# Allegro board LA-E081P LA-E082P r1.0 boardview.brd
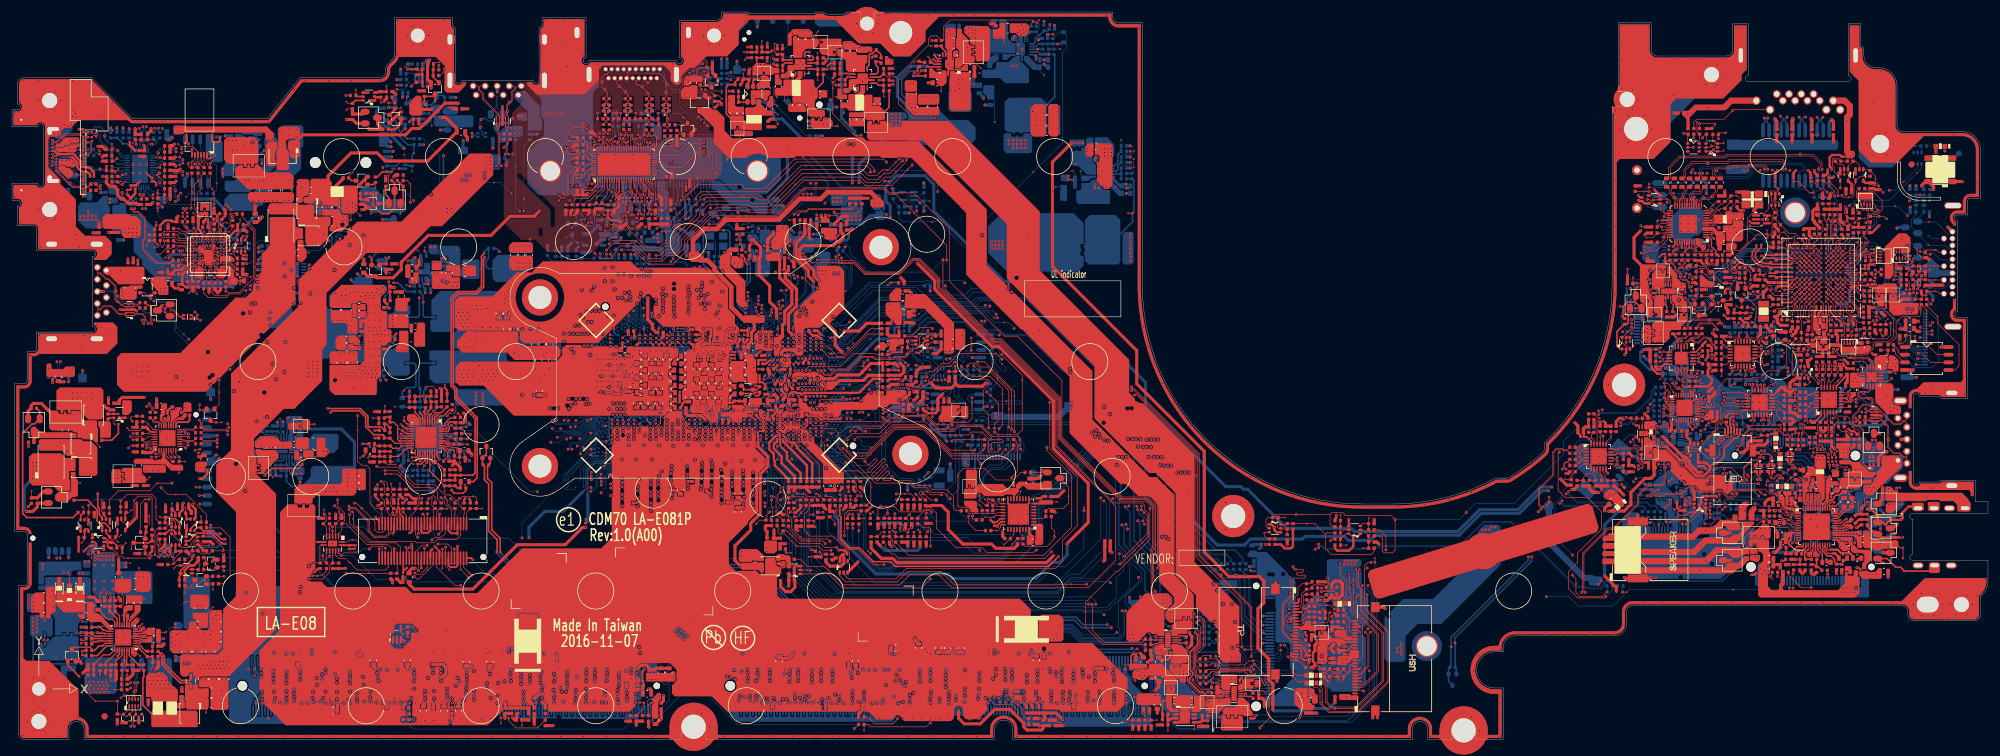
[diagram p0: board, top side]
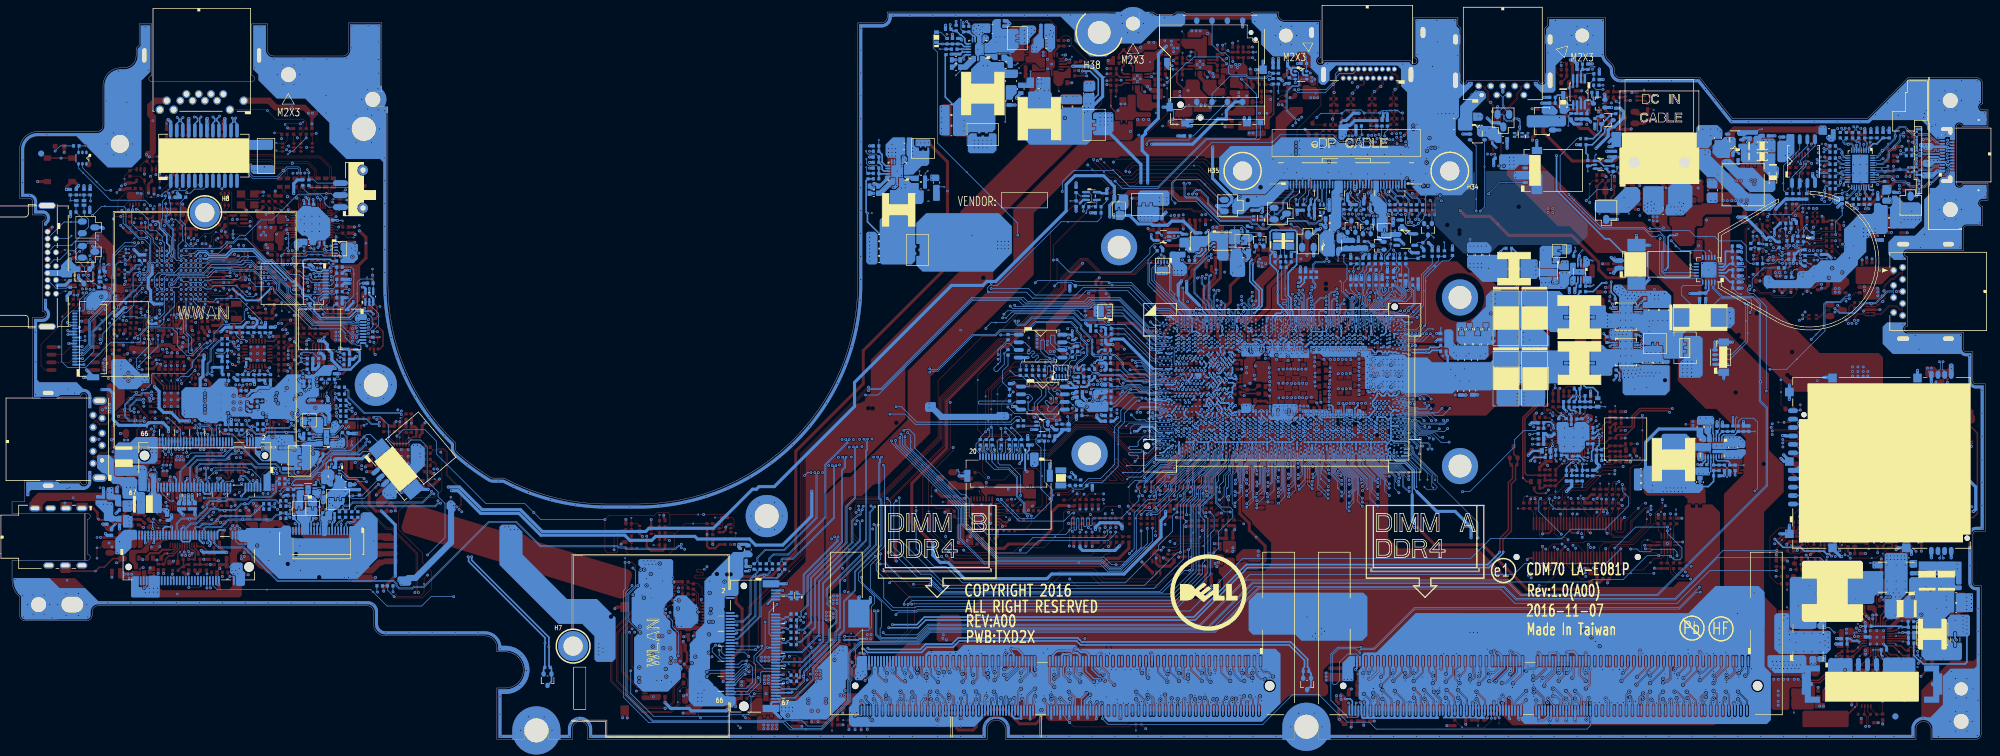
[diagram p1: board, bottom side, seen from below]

Outline 328.05 x 120.8 mm; copper layers: TOP, GND1, IN1, GND2, IN2, IN3, VCC, IN4, GND3, BOTTOM. Coordinates in mm from the lower left corner of the outline.

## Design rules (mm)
net group CLK_ITPXDP_: nets CLK_ITPXDP_N CLK_ITPXDP_P
net group CPU_DP2_0_C: nets CPU_DP2_N0_C CPU_DP2_P0_C
net group CPU_DP2_1_C: nets CPU_DP2_N1_C CPU_DP2_P1_C
net group CPU_DP2_2_C: nets CPU_DP2_N2_C CPU_DP2_P2_C
net group CPU_DP2_3_C: nets CPU_DP2_N3_C CPU_DP2_P3_C
net group CPU_DP2_AUX_C: nets CPU_DP2_AUXN_C CPU_DP2_AUXP_C
net group CPU_DP3_AUX: nets CPU_DP3_AUXN CPU_DP3_AUXP
net group CRT_CTL_5_10: nets CLK_DDC2_CRT DAT_DDC2_CRT
net group CSI_ISL88738: nets CSIN_ISL88738 CSIP_ISL88738
net group CSO_ISL88738: nets CSON_ISL88738 CSOP_ISL88738
net group DDR_A_0: nets DDR_A_DQS0 DDR_A_DQS#0
net group DDR_A_1: nets DDR_A_DQS1 DDR_A_DQS#1
net group DDR_A_2: nets DDR_A_DQS2 DDR_A_DQS#2
net group DDR_A_3: nets DDR_A_DQS3 DDR_A_DQS#3
net group DDR_A_4: nets DDR_A_DQS4 DDR_A_DQS#4
net group DDR_A_5: nets DDR_A_DQS5 DDR_A_DQS#5
net group DDR_A_6: nets DDR_A_DQS6 DDR_A_DQS#6
net group DDR_A_7: nets DDR_A_DQS7 DDR_A_DQS#7
net group DDR_A_CLK0: nets DDR_A_CLK0 DDR_A_CLK#0
net group DDR_A_CLK1: nets DDR_A_CLK1 DDR_A_CLK#1
net group DDR_B_0: nets DDR_B_DQS0 DDR_B_DQS#0
net group DDR_B_1: nets DDR_B_DQS1 DDR_B_DQS#1
net group DDR_B_2: nets DDR_B_DQS2 DDR_B_DQS#2
net group DDR_B_3: nets DDR_B_DQS3 DDR_B_DQS#3
net group DDR_B_4: nets DDR_B_DQS4 DDR_B_DQS#4
net group DDR_B_5: nets DDR_B_DQS5 DDR_B_DQS#5
net group DDR_B_6: nets DDR_B_DQS6 DDR_B_DQS#6
net group DDR_B_7: nets DDR_B_DQS7 DDR_B_DQS#7
net group DDR_B_CLK0: nets DDR_B_CLK0 DDR_B_CLK#0
net group DDR_B_CLK1: nets DDR_B_CLK1 DDR_B_CLK#1
net group DIFFPAIR0: nets SML0_SMBCLK SML0_SMBDATA
net group DIFFPAIR2: nets CLK_TP_SIO_I2C_DAT DAT_TP_SIO_I2C_CLK
net group DIFFPAIR3: nets I2C1_SCK_TP I2C1_SDA_TP
net group DIFFPAIR4: nets I2C1_SCK_TP_R I2C1_SDA_TP_R
net group DIFFPAIR5: nets CLK_TP_SIO_R DAT_TP_SIO_R
net group DIFFPAIR9: nets EXPANDER_GPU_SMCLK EXPANDER_GPU_SMDAT
net group DIFFPAIR12: nets ISH_I2C2_SCL_R ISH_I2C2_SDA_R
net group DIFFPAIR13: nets ISH_I2C2_SCL ISH_I2C2_SDA
net group DIFFPAIR14: nets ISPSCL ISPSDA
net group DIFFPAIR18: nets PCH_CL_CLK1 PCH_CL_DATA1
net group DIFFPAIR19: nets UIM_CLK UIM_DATA
net group DIFFPAIR21: nets MUX1_DP_SEL MUX1_USB_SEL
net group DIFFPAIR22: nets UPD1_SMBCLK_Q UPD1_SMBDAT_Q
net group DIFFPAIR31: nets UPD1_SMBCLK UPD1_SMBDAT
net group DIFFPAIR36: nets VCCIO_SENSE VSSIO_SENSE
net group DIFFPAIR37: nets UPD2_SMBCLK UPD2_SMBDAT
net group DIFFPAIR45: nets TUSB546A_SBU1_R TUSB546A_SBU2_R
net group DIFFPAIR46: nets TBTA_SBU1_R TBTA_SBU2_R
net group DIFFPAIR47: nets TBTA_SBU1 TBTA_SBU2
net group DIFFPAIR48: nets TBTA_CC1 TBTA_CC2
net group DIFFPAIR49: nets VCCSENSE VSSSENSE
net group DIFFPAIR50: nets VCC_GT_SENSE VSS_GT_SENSE
net group DP: nets CPU_DP1_AUXN CPU_DP1_AUXP
net group EDP_AUX_C: nets EDP_AUXN_C EDP_AUXP_C
net group EDP_TX0_C: nets EDP_TXN0_C EDP_TXP0_C
net group EDP_TX1_C: nets EDP_TXN1_C EDP_TXP1_C
net group HDMI: nets CPU_DP2_CTRL_CLK CPU_DP2_CTRL_DATA
net group HDMI-CTL: nets HDMI_CTRL_CLK HDMI_CTRL_DATA
net group HDMI_CLK: nets HDMI_CLKN HDMI_CLKP
net group HDMI_L_CLK: nets HDMI_L_CLKN HDMI_L_CLKP
net group HDMI_L_TX_0: nets HDMI_L_TX_N0 HDMI_L_TX_P0
net group HDMI_L_TX_1: nets HDMI_L_TX_N1 HDMI_L_TX_P1
net group HDMI_L_TX_2: nets HDMI_L_TX_N2 HDMI_L_TX_P2
net group HDMI_TX_0: nets HDMI_TX_N0 HDMI_TX_P0
net group HDMI_TX_1: nets HDMI_TX_N1 HDMI_TX_P1
net group HDMI_TX_2: nets HDMI_TX_N2 HDMI_TX_P2
net group LAN_MDI0: nets LAN_MDIN0 LAN_MDIP0
net group LAN_MDI0_L: nets LAN_MDIN0_L LAN_MDIP0_L
net group LAN_MDI1: nets LAN_MDIN1 LAN_MDIP1
net group LAN_MDI1_L: nets LAN_MDIN1_L LAN_MDIP1_L
net group LAN_MDI2: nets LAN_MDIN2 LAN_MDIP2
net group LAN_MDI2_L: nets LAN_MDIN2_L LAN_MDIP2_L
net group LAN_MDI3: nets LAN_MDIN3 LAN_MDIP3
net group LAN_MDI3_L: nets LAN_MDIN3_L LAN_MDIP3_L
net group PCIE_RCOMP: nets PCIE_RCOMPN PCIE_RCOMPP
net group REM_DIODE1_: nets REM_DIODE1_N REM_DIODE1_P
net group REM_DIODE2_: nets REM_DIODE2_N REM_DIODE2_P
net group REM_DIODE4_: nets REM_DIODE4_N REM_DIODE4_P
net group RJ45_MDI0: nets RJ45_MDIN0 RJ45_MDIP0
net group RJ45_MDI1: nets RJ45_MDIN1 RJ45_MDIP1
net group RJ45_MDI2: nets RJ45_MDIN2 RJ45_MDIP2
net group RJ45_MDI3: nets RJ45_MDIN3 RJ45_MDIP3
net group SD/MMCDAT1/RCLK-: nets SD/MMCDAT0/RCLK+ SD/MMCDAT1/RCLK-
net group SD/MMCDAT1/RCLK-_R: nets SD/MMCDAT0/RCLK+_R SD/MMCDAT1/RCLK-_R
net group SD_UHS2_D0: nets SD_UHS2_D0N SD_UHS2_D0P
net group SD_UHS2_D1: nets SD_UHS2_D1N SD_UHS2_D1P
net group SW2_DP1_0_C: nets SW2_DP1_N0_C SW2_DP1_P0_C
net group SW2_DP1_1_C: nets SW2_DP1_N1_C SW2_DP1_P1_C
net group SW2_DP1_2_C: nets SW2_DP1_N2_C SW2_DP1_P2_C
net group SW2_DP1_3_C: nets SW2_DP1_N3_C SW2_DP1_P3_C
net group SW2_DP1_AUX_C: nets SW2_DP1_AUXN_C SW2_DP1_AUXP_C
net group SW2_DP2_0_C: nets SW2_DP2_N0_C SW2_DP2_P0_C
net group SW2_DP2_1_C: nets SW2_DP2_N1_C SW2_DP2_P1_C
net group SW2_DP2_2_C: nets SW2_DP2_N2_C SW2_DP2_P2_C
net group SW2_DP2_3_C: nets SW2_DP2_N3_C SW2_DP2_P3_C
net group SW2_DP2_AUX_C: nets SW2_DP2_AUXN_C SW2_DP2_AUXP_C
net group SW2_DP3_0_C: nets SW2_DP3_N0_C SW2_DP3_P0_C
net group SW2_DP3_1_C: nets SW2_DP3_N1_C SW2_DP3_P1_C
net group SW2_DP3_AUX_C: nets SW2_DP3_AUXN_C SW2_DP3_AUXP_C
net group SW_USB20_1: nets SW_USB20_N1 SW_USB20_P1
net group THERMAL: nets POWER_SW#_MB POWER_SW_IN#
net group USB3_PRX_C_DTX_6: nets USB3_PRX_C_DTX_N6 USB3_PRX_C_DTX_P6
net group USB3_PRX_C_RD_DTX_1: nets USB3_PRX_C_RD_DTX_N1 USB3_PRX_C_RD_DTX_P1
net group USB3_PRX_L_DTX_2: nets USB3_PRX_L_DTX_N2 USB3_PRX_L_DTX_P2
net group USB3_PRX_RD_DTX_1: nets USB3_PRX_RD_DTX_N1 USB3_PRX_RD_DTX_P1
net group USB3_PTX_C_DRX_1: nets USB3_PTX_C_DRX_N1 USB3_PTX_C_DRX_P1
net group USB3_PTX_C_DRX_2: nets USB3_PTX_C_DRX_N2 USB3_PTX_C_DRX_P2
net group USB3_PTX_C_DRX_3: nets USB3_PTX_C_DRX_N3 USB3_PTX_C_DRX_P3
net group USB3_PTX_C_DRX_4: nets USB3_PTX_C_DRX_N4 USB3_PTX_C_DRX_P4
net group USB3_PTX_C_DRX_6: nets USB3_PTX_C_DRX_N6 USB3_PTX_C_DRX_P6
net group USB3_PTX_C_RD_DRX_1: nets USB3_PTX_C_RD_DRX_N1 USB3_PTX_C_RD_DRX_P1
net group USB3_PTX_L_DRX_2: nets USB3_PTX_L_DRX_N2 USB3_PTX_L_DRX_P2
net group USB3_PTX_RD_DRX_1: nets USB3_PTX_RD_DRX_N1 USB3_PTX_RD_DRX_P1
net group USB20_1_R: nets USB20_N1_R USB20_P1_R
net group USB20_2_R: nets USB20_N2_R USB20_P2_R
net group USB20_3_R: nets USB20_N3_R USB20_P3_R
net group USB20_4_L: nets USB20_N4_L USB20_P4_L
net group USB20_5_R: nets USB20_N5_R USB20_P5_R
net group USB20_7_L: nets USB20_N7_L USB20_P7_L
net group USB20_8_R: nets USB20_N8_R USB20_P8_R
net group 12: nets H_VCCST_PWRGD_XDP
net group 15: nets ESPI_CLK_5105
net group 20: nets +DDR_VREF_A_DQ +DDR_VREF_B_CA +DDR_VREF_B_DQ +DDR_VREF_CA DDR_DRAMRST# DDR_DRAMRST#_R INT_SPK_L+ INT_SPK_L- INT_SPK_R+ INT_SPK_R- INT_SPKR_L+ INT_SPKR_L- INT_SPKR_R+ INT_SPKR_R-
net group 5225: nets CAM_MIC_CBL_DET# CLK_ITPXDP_N_R CLK_ITPXDP_P_R CLK_PCIE_N0 CLK_PCIE_N1 CLK_PCIE_N2 CLK_PCIE_N3 CLK_PCIE_N4 CLK_PCIE_N5 CLK_PCIE_P0 CLK_PCIE_P1 CLK_PCIE_P2 CLK_PCIE_P3 CLK_PCIE_P4 CLK_PCIE_P5 CPU_DP1_CTRL_CLK CPU_DP1_CTRL_DATA CPU_DP1_N0 CPU_DP1_N1 CPU_DP1_N2 CPU_DP1_N3 CPU_DP1_P0 CPU_DP1_P1 CPU_DP1_P2 CPU_DP1_P3 CPU_DP2_AUXN CPU_DP2_AUXP CPU_DP2_N0 CPU_DP2_N1 CPU_DP2_N2 CPU_DP2_N3 CPU_DP2_P0 CPU_DP2_P1 CPU_DP2_P2 CPU_DP2_P3 EDP_AUXN EDP_AUXP EDP_BIA_PWM EDP_HPD EDP_TXN0 EDP_TXN1 EDP_TXP0 EDP_TXP1 ENVDD_PCH LPSS_UART2_RXD LPSS_UART2_TXD PANEL_BKLEN PCIE_PRX_DTX_N1 PCIE_PRX_DTX_N3 PCIE_PRX_DTX_N4 PCIE_PRX_DTX_N11 PCIE_PRX_DTX_N12 PCIE_PRX_DTX_P1 PCIE_PRX_DTX_P3 PCIE_PRX_DTX_P4 PCIE_PRX_DTX_P11 PCIE_PRX_DTX_P12 PCIE_PRX_RD_DTX_N11 PCIE_PRX_RD_DTX_N12 PCIE_PRX_RD_DTX_P11 PCIE_PRX_RD_DTX_P12 PCIE_PTX_DRX_N1 PCIE_PTX_DRX_N3 PCIE_PTX_DRX_N4 PCIE_PTX_DRX_N8 PCIE_PTX_DRX_N9 PCIE_PTX_DRX_N11 PCIE_PTX_DRX_N12 PCIE_PTX_DRX_P1 PCIE_PTX_DRX_P3 PCIE_PTX_DRX_P4 PCIE_PTX_DRX_P8 PCIE_PTX_DRX_P9 PCIE_PTX_DRX_P11 PCIE_PTX_DRX_P12 PCIE_PTX_RD_DRX_N11 PCIE_PTX_RD_DRX_P11 SATA_PRX_DTX_N0 SATA_PRX_DTX_P0 SW2_DP1_AUXN SW2_DP1_AUXP SW2_DP1_N0 SW2_DP1_N1 SW2_DP1_N2 SW2_DP1_N3 SW2_DP1_P0 SW2_DP1_P1 SW2_DP1_P2 SW2_DP1_P3 SW2_DP2_AUXN SW2_DP2_AUXP SW2_DP2_N0 SW2_DP2_N1 SW2_DP2_N2 SW2_DP2_N3 SW2_DP2_P0 SW2_DP2_P1 SW2_DP2_P2 SW2_DP2_P3 SW2_DP3_AUXN SW2_DP3_AUXP SW2_DP3_N0 SW2_DP3_N1 SW2_DP3_P0 SW2_DP3_P1 USB3_PRX_DTX_N1 USB3_PRX_DTX_N2 USB3_PRX_DTX_N3 USB3_PRX_DTX_N4 USB3_PRX_DTX_N6 USB3_PRX_DTX_P1 USB3_PRX_DTX_P2 USB3_PRX_DTX_P3 USB3_PRX_DTX_P4 USB3_PRX_DTX_P6 USB3_PTX_DRX_N1 USB3_PTX_DRX_N2 USB3_PTX_DRX_N3 USB3_PTX_DRX_N4 USB3_PTX_DRX_N6 USB3_PTX_DRX_P1 USB3_PTX_DRX_P2 USB3_PTX_DRX_P3 USB3_PTX_DRX_P4 USB3_PTX_DRX_P6 USB20_N1 USB20_N2 USB20_N3 USB20_N4 USB20_N5 USB20_N7 USB20_N8 USB20_N9 USB20_N10 USB20_P1 USB20_P2 USB20_P3 USB20_P4 USB20_P5 USB20_P7 USB20_P8 USB20_P9 USB20_P10
net group ADUIO: nets RING2 RING2_R SLEEVE SLEEVE_R
net group AUDIO: nets +LINE1-VREFO-L +LINE1-VREFO-R AUD_HP_NB_SENSE AUD_HP_OUT_L AUD_HP_OUT_L1 AUD_HP_OUT_R AUD_HP_OUT_R1 AUD_SENSE_A HP_OUT_L HP_OUT_R LINE1_L LINE1_R
net group B+: nets +PWR_SRC
net group CARD_READER: nets SD/MMCCD# SD/MMCCLK SD/MMCCLK_R SD/MMCCMD SD/MMCCMD_R SD/MMCDAT2 SD/MMCDAT2_R SD/MMCDAT3 SD/MMCDAT3_R SD_GPIO SDWP SDWP_Q
net group CLK: nets CLKREQ_PCIE#0 CLKREQ_PCIE#1 CLKREQ_PCIE#2 CLKREQ_PCIE#3 CLKREQ_PCIE#4 CLKREQ_PCIE#5 CPU_XDP_TCLK JTAG_CLK MEC_XTAL1 MEC_XTAL2 MEC_XTAL2_R MSCLK PCH_JTAG_TCK PCI_CLK_LPC1 SUSCLK SUSCLK_R WIGIG_32KHZ XDP_JTAGX XTAL24_IN XTAL24_OUT XTAL24_OUT_R XTALI XTALO XTALO_R
net group CPU: nets H_CATERR# H_PROCHOT# H_PROCHOT#_R H_PROCHOT#_R1 H_THERMTRIP# PCH_PLTRST# PCH_PLTRST#_5105 PCH_PLTRST#_AND PCH_PLTRST#_EC PLTRST_LAN# PLTRST_TPM# SHD_IO0 SHD_IO0_R1 SHD_IO0_R2 SHD_IO1 SHD_IO1_R1 SHD_IO1_R2 SHD_IO2 SHD_IO2_R1 SHD_IO2_R2 SHD_IO3 SHD_IO3_R1 SHD_IO3_R2 THERMATRIP2# VCCST_PWRGD XDP_OBS0 XDP_OBS0_R XDP_OBS1 XDP_OBS1_R
net group CRITICAL: nets INTRUDER# PCH_DPWROK PCH_PCIE_WAKE# PCH_RSMRST# PCIE_WAKE# PCIE_WAKE#_R RESET_OUT#_R SIO_PWRBTN# SIO_RCIN# SIO_RCIN#_EC SRTCRST# SYS_RESET# SYS_RESET#_R UPD1_ALERT#
net group CRT_DAC_20_30: nets BLUE BLUE_CRT GREEN GREEN_CRT RED RED_CRT
net group CRT_SYNC_12_20: nets HSYNC_CONN HSYNC_CRT VSYNC_CONN VSYNC_CRT
net group CTL-LINK: nets PCH_CL_RST1#
net group DDRADD_ALERT_10/11_19/20_25: nets DDR_A_ACT# DDR_A_ALERT# DDR_A_BA0 DDR_A_BA1 DDR_A_BG0 DDR_A_BG1 DDR_A_MA0 DDR_A_MA1 DDR_A_MA2 DDR_A_MA3 DDR_A_MA4 DDR_A_MA5 DDR_A_MA6 DDR_A_MA7 DDR_A_MA8 DDR_A_MA9 DDR_A_MA10 DDR_A_MA11 DDR_A_MA12 DDR_A_MA13 DDR_A_MA14 DDR_A_MA15 DDR_A_MA16 DDR_A_PARITY DDR_B_ACT# DDR_B_ALERT# DDR_B_BA0 DDR_B_BA1 DDR_B_BG0 DDR_B_BG1 DDR_B_MA0 DDR_B_MA1 DDR_B_MA2 DDR_B_MA3 DDR_B_MA4 DDR_B_MA5 DDR_B_MA6 DDR_B_MA7 DDR_B_MA8 DDR_B_MA9 DDR_B_MA10 DDR_B_MA11 DDR_B_MA12 DDR_B_MA13 DDR_B_MA14 DDR_B_MA15 DDR_B_MA16 DDR_B_PARITY
net group DDRCTL_CKE_10/11_19/20_25: nets DDR_A_CKE0 DDR_A_CKE1 DDR_A_CS#0 DDR_A_CS#1 DDR_A_ODT0 DDR_A_ODT1 DDR_B_CKE0 DDR_B_CKE1 DDR_B_CS#0 DDR_B_CS#1 DDR_B_ODT0 DDR_B_ODT1
net group DDRD0_19/8.5/10_19/20_25: nets DDR_A_D0 DDR_A_D1 DDR_A_D2 DDR_A_D3 DDR_A_D4 DDR_A_D5 DDR_A_D6 DDR_A_D7 DDR_A_D16 DDR_A_D17 DDR_A_D18 DDR_A_D19 DDR_A_D20 DDR_A_D21 DDR_A_D22 DDR_A_D23 DDR_A_D32 DDR_A_D33 DDR_A_D34 DDR_A_D35 DDR_A_D36 DDR_A_D37 DDR_A_D38 DDR_A_D39 DDR_A_D48 DDR_A_D49 DDR_A_D50 DDR_A_D51 DDR_A_D52 DDR_A_D53 DDR_A_D54 DDR_A_D55 DDR_B_D0 DDR_B_D1 DDR_B_D2 DDR_B_D3 DDR_B_D4 DDR_B_D5 DDR_B_D6 DDR_B_D7 DDR_B_D16 DDR_B_D17 DDR_B_D18 DDR_B_D19 DDR_B_D20 DDR_B_D21 DDR_B_D22 DDR_B_D23 DDR_B_D32 DDR_B_D33 DDR_B_D34 DDR_B_D35 DDR_B_D36 DDR_B_D37 DDR_B_D38 DDR_B_D39 DDR_B_D48 DDR_B_D49 DDR_B_D50 DDR_B_D51 DDR_B_D52 DDR_B_D53 DDR_B_D54 DDR_B_D55
net group DDRD1_19/8.5/10_19/20_25: nets DDR_A_D8 DDR_A_D9 DDR_A_D10 DDR_A_D11 DDR_A_D12 DDR_A_D13 DDR_A_D14 DDR_A_D15 DDR_A_D24 DDR_A_D25 DDR_A_D26 DDR_A_D27 DDR_A_D28 DDR_A_D29 DDR_A_D30 DDR_A_D31 DDR_A_D40 DDR_A_D41 DDR_A_D42 DDR_A_D43 DDR_A_D44 DDR_A_D45 DDR_A_D46 DDR_A_D47 DDR_A_D56 DDR_A_D57 DDR_A_D58 DDR_A_D59 DDR_A_D60 DDR_A_D61 DDR_A_D62 DDR_A_D63 DDR_B_D8 DDR_B_D9 DDR_B_D10 DDR_B_D11 DDR_B_D12 DDR_B_D13 DDR_B_D14 DDR_B_D15 DDR_B_D24 DDR_B_D25 DDR_B_D26 DDR_B_D27 DDR_B_D28 DDR_B_D29 DDR_B_D30 DDR_B_D31 DDR_B_D40 DDR_B_D41 DDR_B_D42 DDR_B_D43 DDR_B_D44 DDR_B_D45 DDR_B_D46 DDR_B_D47 DDR_B_D56 DDR_B_D57 DDR_B_D58 DDR_B_D59 DDR_B_D60 DDR_B_D61 DDR_B_D62 DDR_B_D63
net group DIFFPAIR1: nets SML1_SMBCLK
net group DIFFPAIR8: nets DDR_XDP_WAN_SMBCLK
net group DIFFPAIR15: nets MEM_SMBCLK
net group DIFFPAIR16: nets PBAT_CHARGER_SMBCLK
net group DIFFPAIR17: nets PBAT_SMBCLK_C
net group DIFFPAIR20: nets USH_SMBCLK
net group ESPI: nets ESPI_CS# ESPI_IO0 ESPI_IO0_R ESPI_IO1 ESPI_IO1_R ESPI_IO2 ESPI_IO2_R ESPI_IO3 ESPI_IO3_R
net group GND: nets GNDA
net group HDA: nets DMIC_CLK0 DMIC_CLK_CODEC HDA_BIT_CLK HDA_BIT_CLK_R
net group HDA_5_15: nets DMIC0 HDA_RST# HDA_RST#_R HDA_SDIN0 HDA_SDIN0_R HDA_SDOUT HDA_SDOUT_R HDA_SYNC HDA_SYNC_R
net group PCIE: nets PCIE_PRX_C_DTX_N1 PCIE_PRX_C_DTX_N9 PCIE_PRX_C_DTX_N11 PCIE_PRX_C_DTX_N12 PCIE_PRX_C_DTX_P1 PCIE_PRX_C_DTX_P9 PCIE_PRX_C_DTX_P11 PCIE_PRX_C_DTX_P12 PCIE_PRX_C_RD_DTX_N8 PCIE_PRX_C_RD_DTX_N11 PCIE_PRX_C_RD_DTX_N12 PCIE_PRX_C_RD_DTX_P8 PCIE_PRX_C_RD_DTX_P11 PCIE_PRX_C_RD_DTX_P12 PCIE_PRX_DTX_N8 PCIE_PRX_DTX_N9 PCIE_PRX_DTX_P8 PCIE_PRX_DTX_P9 PCIE_PRX_RD_DTX_N8 PCIE_PRX_RD_DTX_P8 PCIE_PTX_C_DRX_N1 PCIE_PTX_C_DRX_N3 PCIE_PTX_C_DRX_N4 PCIE_PTX_C_DRX_N8 PCIE_PTX_C_DRX_N9 PCIE_PTX_C_DRX_N11 PCIE_PTX_C_DRX_N12 PCIE_PTX_C_DRX_P1 PCIE_PTX_C_DRX_P3 PCIE_PTX_C_DRX_P4 PCIE_PTX_C_DRX_P8 PCIE_PTX_C_DRX_P9 PCIE_PTX_C_DRX_P11 PCIE_PTX_C_DRX_P12 PCIE_PTX_C_RD_DRX_N8 PCIE_PTX_C_RD_DRX_N11 PCIE_PTX_C_RD_DRX_N12 PCIE_PTX_C_RD_DRX_P8 PCIE_PTX_C_RD_DRX_P11 PCIE_PTX_C_RD_DRX_P12 PCIE_PTX_RD_DRX_N8 PCIE_PTX_RD_DRX_N12 PCIE_PTX_RD_DRX_P8 PCIE_PTX_RD_DRX_P12
net group POWER: nets +1.2V_MEM
net group RCOMP: nets CFG_RCOMP CPU_POPIRCOMP EDP_COMP EDRAM_OPIO_RCOMP EMMC_RCOMP EOPIO_RCOMP PCH_POPIRCOMP SD_RCOMP SM_RCOMP0 SM_RCOMP1 SM_RCOMP2 USBCOMP
net group RTC: nets PCH_RTCRST# PCH_RTCX1 PCH_RTCX2 PCH_RTCX2_R
net group SATA: nets SATA_PRX_C_DTX_N0 SATA_PRX_C_DTX_P0 SATA_PRX_C_RD_DTX_N0 SATA_PRX_C_RD_DTX_P0 SATA_PRX_RD_DTX_N0 SATA_PRX_RD_DTX_P0 SATA_PTX_C_DRX_N0 SATA_PTX_C_DRX_P0 SATA_PTX_C_RD_DRX_N0 SATA_PTX_C_RD_DRX_P0 SATA_PTX_DRX_N0 SATA_PTX_DRX_P0 SATA_PTX_RD_DRX_N0 SATA_PTX_RD_DRX_P0
net group SMBUS: nets DDR_XDP_WAN_SMBDAT GPP_C5 MEM_SMBDATA PBAT_CHARGER_SMBDAT PBAT_SMBDAT_C PCH_SMB_ALERT# SML1_SMBDATA UPD1_SMBUS_ALERT# UPD2_ALERT# USH_SMBDAT
net group SPI: nets PCH_SPI_CLK PCH_SPI_CLK_0_R PCH_SPI_CLK_1_R PCH_SPI_CLK_2_R PCH_SPI_CLK_R1 PCH_SPI_CS#0 PCH_SPI_CS#0_R1 PCH_SPI_CS#0_R2 PCH_SPI_CS#1 PCH_SPI_CS#1_R1 PCH_SPI_CS#1_R2 PCH_SPI_CS#2 PCH_SPI_CS#2_R PCH_SPI_D0 PCH_SPI_D0_0_R PCH_SPI_D0_1_R PCH_SPI_D0_2_R PCH_SPI_D0_R1 PCH_SPI_D1 PCH_SPI_D1_0_R PCH_SPI_D1_1_R PCH_SPI_D1_2_R PCH_SPI_D1_R1 PCH_SPI_D2 PCH_SPI_D2_0_R PCH_SPI_D2_1_R PCH_SPI_D2_R1 PCH_SPI_D3 PCH_SPI_D3_0_R PCH_SPI_D3_1_R PCH_SPI_D3_R1 PCH_SPI_DO2_XDP PCH_SPI_DO_XDP TBTA_ROM_CLK_PD TBTA_ROM_CLK_PD_R TBTA_ROM_CS#_PD TBTA_ROM_CS#_PD_R TBTA_ROM_DI_PD TBTA_ROM_DI_PD_R TBTA_ROM_DO_PD TBTA_ROM_DO_PD_R
net group SVID: nets H_CPU_SVIDALRT# PECI_EC PECI_EC_R VIDALERT_N VIDALERT_N_B VIDSCLK VIDSCLK_B VIDSOUT VIDSOUT_B
net group TBTA-USB30: nets TBTA_AUXN_C TBTA_AUXP_C TBTA_BOT_N TBTA_BOT_N_R TBTA_BOT_P TBTA_BOT_P_R TBTA_RX1N TBTA_RX1P TBTA_RX2N TBTA_RX2P TBTA_TOP_N TBTA_TOP_N_R TBTA_TOP_P TBTA_TOP_P_R TBTA_TX1N TBTA_TX1N_C TBTA_TX1P TBTA_TX1P_C TBTA_TX2N TBTA_TX2N_C TBTA_TX2P TBTA_TX2P_C
net group UIM: nets UIM_RESET
nets with their own width: min track width 0.254; nets +1.0VO_DSW +1.2V_MEM_CPUCLK AUD_PC_BEEP BAT1_LED# BAT2_LED# BATT_WHITE# BATT_YELLOW# BEEP_R N16400770 N18762401 N18762411 N18762416 N18762426 N18762428 N18762438 N20151644 N27077001 N132005053 SPKR_R VDDP_ISL88738 XCLK_BIASREF
nets with their own width: min track width 0.305; nets +RREF
nets with their own width: min track width 0.508; nets +1.0V_AMPHYPLL +1.0V_APLL +1.0V_APLLEBB +1.0V_CLK1 +1.0V_CLK2 +1.0V_CLK3 +1.0V_CLK4 +1.0V_CLK5 +1.0V_CLK6 +1.0V_DTS +1.0V_PRIM +1.0V_PRIM_XDP +1.0V_VCCST +1.0V_VCCST_C +1.0V_VCCSTG +1.0V_VCCSTG_C +1.2V_LDO +1.8V_RUN +1.8V_RUN_CARD +3.3V_1.8V_PGPPA +3.3V_1.8V_PGPPG +3.3V_ALW +3.3V_ALW2 +3.3V_ALW_DSW +3.3V_ALW_UE1 +3.3V_CAM +3.3V_CPS +3.3V_LAN_OUT +3.3V_MMI_AUX +3.3V_PGPPB +3.3V_PGPPC +3.3V_PGPPD +3.3V_PGPPE +3.3V_RTC_LDO +3.3V_RUN +3.3V_RUN_AUDIO +3.3V_RUN_AUDIO_DVDD +3.3V_RUN_AUDIO_IO +3.3V_RUN_AUDIO_UZ5 +3.3V_SPI +3.3V_TP +3.3V_VCCHDA +5V_ALW +5V_ALW2 +5V_RUN +COINCELL +DDR_VREF_A_CA +DV33_18 +GND_CHASSIS +MIC2-VREFO +RSVD_VCC3P3_1 +RTC_CELL +SDREG2 +VCC_CORE +VCC_GT +VCC_SA +VCC_SFR_OC +VDD_DAC_33 +VDDA_AVDD1 +VSS_PLL GND
nets with their own width: min track width 0.762; nets +0.9V_LAN +1.0V_SRAM +2.5V_MEM +3.3V_VDD_PIC +3.3V_VDD_PIC_PDA +3.3V_VGA BGATE_ISL88738 LG1_ISL88738 LG2_ISL88738 LX1_ISL88738 LX2_ISL88738 UG1_ISL88738 UG2_ISL88738
nets with their own width: min track width 1.016; nets +0.6V_DDR_VTT +1.8V_PGPPF +1.8V_PRIM +1.8V_RUN_UZ8 +3.3V_ALW_PCH +3.3V_ALW_PCH_UZ3 +3.3V_LAN +3.3V_LAN_UZ2 +3.3V_RUN_CARD +5V_TSP +CRT_VCC +VHDMI_VCC
nets with their own width: min track width 1.27; nets +3.3V_MMI_IN
nets with their own width: min track width 1.524; nets +5V_HDD +5V_HDD_UZ23 +EDP_VDD +LCDVDD
nets with their own width: min track width 2.032; nets +BL_PWR_SRC +USB_EX2_PWR +USB_EX3_PWR
nets with their own width: min track width 2.286; nets +3.3V_HDD +3.3V_WLAN +3.3V_WWAN_UZ2
nets with their own width: min track width 2.54; nets +5V_RUN_AUDIO +5V_RUN_AUDIO_UZ5 +5V_RUN_PVDD_L +5V_RUN_UZ4 +5V_USB_CHG_PWR
nets with their own width: min track width 2.794; nets +1.0V_PRIM_CORE +3.3V_WLAN_UZ4 +3.3V_WWAN
nets with their own width: min track width 3.048; nets +1.0V_MPHYAON +1.0V_MPHYGT +3.3V_HDD_M2
nets with their own width: min track width 3.302; nets +1.0VS_VCCIO
nets with their own width: min track width 3.556; nets +3.3V_RUN_UZ3 +5V_ALW_PDA

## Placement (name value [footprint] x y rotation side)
CA1  680P_0402_50V7K  [C_0402]  313.82 40.29 270 bottom
CA2  330P_0402_50V8J  [C_0402]  312.62 33.55 270 top
CA3  330P_0402_50V8J  [C_0402]  311.54 34.82 270 bottom
CA4  680P_0402_50V7K  [C_0402]  311.97 40.28 0 bottom
CA5  100P_0402_50V8J  [C_0402]  113.67 88.8 270 bottom
CA6  100P_0402_50V8J  [C_0402]  114.69 88.8 270 bottom
CA7  100P_0201_25V7K  [C_0201]  111.89 91.84 0 top
CA8  0.1U_0201_10V6K  [C_0201]  304.04 33.2 270 top
CA9  10U_0603_10V6M  [C_0603]  305.63 31.7 180 top
CA10  0.1U_0201_10V6K  [C_0201]  295.28 38.33 90 top
CA12  680P_0402_50V7K  [C_0402]  312.3 36.67 270 bottom
CA13  680P_0402_50V7K  [C_0402]  310.65 41.17 270 bottom
CA19  1000P_0402_50V7K  [C_0402]  297.69 39.21 270 bottom
CA22  1000P_0402_50V7K  [C_0402]  300.36 39.21 270 bottom
CA23  1000P_0402_50V7K  [C_0402]  299.47 39.21 270 bottom
CA24  1000P_0402_50V7K  [C_0402]  298.58 39.21 270 bottom
CA25  10U_0603_10V6M  [C_0603]  300.55 29.42 0 top
CA27  0.1U_0402_25V6  [C_0402]  299.65 29.93 180 top
CA28  0.1U_0402_25V6  [C_0402]  296.85 29.93 0 top
CA29  1U_0603_10V6K  [C_0603]  304.17 38.69 90 top
CA31  1U_0603_10V6K  [C_0603]  296.8 39.9 180 top
CA33  10P_0402_50V8J  [C_0402]  291.75 37.1 180 top
CA35  2.2U_0402_6.3V6M  [C_0402]  306.76 34.31 0 top
CA41  0.1U_0402_25V6  [C_0402]  295.34 30.83 270 top
CA43  10U_0603_10V6M  [C_0603]  305.63 30.12 0 top
CA44  10U_0603_10V6M  [C_0603]  303.28 30.12 0 top
CA45  0.1U_0201_10V6K  [C_0201]  300.14 41.29 180 top
CA46  10U_0603_10V6M  [C_0603]  300.23 42.18 180 top
CA47  0.1U_0201_10V6K  [C_0201]  298.04 41.29 0 top
CA48  10U_0603_10V6M  [C_0603]  298.84 44.73 180 top
CA49  1U_0603_10V6K  [C_0603]  305.44 38.69 90 top
CA51  10U_0603_10V6M  [C_0603]  306.58 33.23 0 top
CA52  10U_0603_10V6M  [C_0603]  304.17 41.1 90 top
CA53  10U_0603_10V6M  [C_0603]  294.14 36.02 180 top
CA54  10P_0402_50V8J  [C_0402]  291.75 37.99 180 top
CA55  0.1U_0201_10V6K  [C_0201]  295.28 33.77 270 top
CA56  10U_0603_10V6M  [C_0603]  294.52 33.8 180 top
CA57  0.1U_0201_10V6K  [C_0201]  301.4 40.21 0 top
CA58  10U_0603_10V6M  [C_0603]  301.44 41.42 0 top
CA59  10U_0603_10V6M  [C_0603]  310.08 27.89 0 top
CA60  0.1U_0201_10V6K  [C_0201]  306.84 27.67 90 top
CA61  10U_0603_10V6M  [C_0603]  293.76 39.92 180 top
CA62  100P_0402_50V8J  [C_0402]  296.8 29.05 270 top
CA63  12P_0402_50V8J  [C_0402]  276.74 68.29 270 top
CA64  68P_0402_50V8J  [C_0402]  275.72 68.29 270 top
CA65  12P_0402_50V8J  [C_0402]  272.62 45.99 180 top
CA66  68P_0402_50V8J  [C_0402]  272.62 45.1 180 top
CA67  12P_0402_50V8J  [C_0402]  272.42 78.5 90 top
CA68  68P_0402_50V8J  [C_0402]  271.53 78.5 90 top
CA69  33P_0402_50V8J  [C_0402]  302.27 37.31 270 bottom
CA72  100P_0402_50V8J  [C_0402]  299.6 28.67 270 top
CC7  33P_0402_50V8J  [C_0402]  150.42 53.8 0 bottom
CC8  33P_0402_50V8J  [C_0402]  151.14 64.41 90 bottom
CC9  0.1U_0201_10V6K  [C_0201]  152.02 66.95 270 bottom
CC10  0.1U_0201_10V6K  [C_0201]  151.14 58.57 180 bottom
CC21  15P_0402_50V8J  [C_0402]  116.57 80.21 180 bottom
CC22  15P_0402_50V8J  [C_0402]  117.44 80.21 0 bottom
CC23  12P_0402_50V8J  [C_0402]  149.61 42.18 180 bottom
CC24  1U_0402_6.3V6K  [C_0402]  134.75 39.78 270 top
CC25  1U_0402_6.3V6K  [C_0402]  153.74 52.36 270 bottom
CC26  12P_0402_50V8J  [C_0402]  152.41 43.58 180 bottom
CC27  47P_0402_50V8J  [C_0402]  127.02 35.51 180 top
CC28  0.1U_0201_10V6K  [C_0201]  64.9 27.68 270 top
CC29  0.1U_0201_10V6K  [C_0201]  64.14 38.52 90 top
CC30  0.1U_0201_10V6K  [C_0201]  56.01 32.25 270 top
CC32  0.1U_0402_25V6  [C_0402]  63.89 27.59 270 top
CC33  0.1U_0402_25V6  [C_0402]  62.36 38.36 90 top
CC176  10U_0402_6.3V6M  [C_0402]  115.32 42.19 270 top
CC177  10U_0402_6.3V6M  [C_0402]  112.91 41.93 90 top
CC178  10U_0402_6.3V6M  [C_0402]  118.75 38.5 90 top
CC179  10U_0402_6.3V6M  [C_0402]  103.15 38.34 90 top
CC195  1U_0402_6.3V6K  [C_0402]  124.47 63.77 180 top
CC199  1U_0402_6.3V6K  [C_0402]  121.4 65.26 180 top
CC202  1U_0402_6.3V6K  [C_0402]  124.27 80.19 180 top
CC203  1U_0402_6.3V6K  [C_0402]  128.35 64.7 270 top
CC204  1U_0402_6.3V6K  [C_0402]  131.91 53.94 270 top
CC205  1U_0402_6.3V6K  [C_0402]  126.42 57.21 270 top
CC206  1U_0402_6.3V6K  [C_0402]  128.3 61.45 0 top
CC207  1U_0402_6.3V6K  [C_0402]  128.64 58.08 180 top
CC208  1U_0402_6.3V6K  [C_0402]  127.59 58.98 180 top
CC209  1U_0402_6.3V6K  [C_0402]  148.09 57.55 0 top
CC210  47U_0805_6.3V6M  [C_0805]  155.33 65.68 0 top
CC211  1U_0402_6.3V6K  [C_0402]  156.06 67.05 0 top
CC212  1U_0402_6.3V6K  [C_0402]  148.34 60.22 0 top
CC213  1U_0402_6.3V6K  [C_0402]  126.77 55.36 0 top
CC214  0.1U_0201_10V6K  [C_0201]  139.2 39.77 270 top
CC215  1U_0402_6.3V6K  [C_0402]  127.51 33.42 270 top
CC216  1U_0402_6.3V6K  [C_0402]  137.6 84.6 0 top
CC217  1U_0402_6.3V6K  [C_0402]  125.01 57.33 90 top
CC218  1U_0402_6.3V6K  [C_0402]  147.35 74.48 0 top
CC219  47U_0805_6.3V6M  [C_0805]  147.24 70.63 0 top
CC220  47U_0805_6.3V6M  [C_0805]  126.77 80.31 90 top
CC221  47U_0805_6.3V6M  [C_0805]  135.01 84.51 90 top
CC222  1U_0402_6.3V6K  [C_0402]  129.81 59.59 180 top
CC223  0.1U_0201_10V6K  [C_0201]  130.83 55.63 180 top
CC224  1U_0402_6.3V6K  [C_0402]  131.73 55.5 90 top
CC225  47U_0805_6.3V6M  [C_0805]  144.53 65.3 0 top
CC226  47U_0805_6.3V6M  [C_0805]  124.47 80.79 180 bottom
CC250  1U_0402_6.3V6K  [C_0402]  120.77 55.28 90 top
CC251  1U_0402_6.3V6K  [C_0402]  119.88 55.28 90 top
CC252  1U_0402_6.3V6K  [C_0402]  119 54 270 top
CC253  1U_0402_6.3V6K  [C_0402]  117.99 54 270 top
CC264  1U_0402_6.3V6K  [C_0402]  147.35 69.23 0 top
CC265  1U_0402_6.3V6K  [C_0402]  128.97 56.44 180 top
CC266  0.01UF_0402_25V7K  [C_0402]  130.18 36.34 270 top
CC269  0.1U_0402_25V6  [C_0402]  65.92 38.36 90 top
CC270  0.1U_0201_10V6K  [C_0201]  126.43 53.14 180 top
CC279  22U_0603_6.3V6M  [C_0603]  135.26 42.81 270 top
CC280  22U_0603_6.3V6M  [C_0603]  136.53 42.81 270 top
CC281  0.1U_0201_10V6K  [C_0201]  156.22 67.84 0 top
CC288  1U_0402_6.3V6K  [C_0402]  121.54 28.97 90 top
CC294  22U_0603_6.3V6M  [C_0603]  111 42.18 270 top
CC295  22U_0603_6.3V6M  [C_0603]  120.53 37.1 90 top
CC296  22U_0603_6.3V6M  [C_0603]  120.53 41.55 270 top
CC297  10U_0402_6.3V6M  [C_0402]  111.88 55.07 180 top
CC300  100P_0402_50V8J  [C_0402]  91.25 80.24 90 bottom
CC301  100P_0402_50V8J  [C_0402]  96.65 77.12 270 bottom
CC302  0.1U_0402_25V6  [C_0402]  147.25 87.45 0 bottom
CC303  0.1U_0402_25V6  [C_0402]  105.8 75.44 90 bottom
CC304  0.1U_0402_25V6  [C_0402]  104.02 75.46 90 bottom
CC305  0.1U_0402_25V6  [C_0402]  102.75 75.44 90 bottom
CC306  0.1U_0402_25V6  [C_0402]  54.74 35.82 90 top
CC307  0.1U_0402_25V6  [C_0402]  66.93 38.36 90 top
CC308  0.1U_0402_25V6  [C_0402]  53.22 29.3 270 top
CC310  0.1U_0402_25V6  [C_0402]  94.62 79.9 90 bottom
CC312  0.1U_0402_25V6  [C_0402]  99.7 79.01 90 bottom
CC313  0.1U_0201_10V6K  [C_0201]  125.5 54.69 270 top
CC314  0.1U_0201_10V6K  [C_0201]  132.63 60.47 270 top
CC316  33P_0402_50V8J  [C_0402]  139.71 42.83 270 top
CC318  33P_0402_50V8J  [C_0402]  149.23 60.22 180 bottom
CC319  33P_0402_50V8J  [C_0402]  145.67 63.39 0 bottom
CC320  33P_0402_50V8J  [C_0402]  148.67 66.12 180 top
CC321  33P_0402_50V8J  [C_0402]  100.59 75.46 90 bottom
CC322  2.2P_0402_50V8C  [C_0402]  122.43 28.97 90 top
CC323  2.2P_0402_50V8C  [C_0402]  144.53 61.36 0 top
CC324  2.2P_0402_50V8C  [C_0402]  125.35 32.53 90 top
CC325  2.2P_0402_50V8C  [C_0402]  126.44 61.51 180 top
CC326  1U_0402_6.3V6K  [C_0402]  150.36 57.73 0 bottom
CC331  2.2P_0402_50V8C  [C_0402]  128.02 36.39 90 top
CC332  2.2P_0402_50V8C  [C_0402]  128.41 31.64 180 top
CC333  2.2P_0402_50V8C  [C_0402]  128.94 40.12 90 top
CD1  10U_0603_10V6M  [C_0603]  65.63 13.84 270 top
CD2  10U_0603_10V6M  [C_0603]  79.34 13.59 270 top
CD3  10U_0603_10V6M  [C_0603]  74.14 4.07 90 top
CD4  10U_0603_10V6M  [C_0603]  68.29 4.07 90 top
CD5  10U_0603_10V6M  [C_0603]  52.61 4.76 0 top
CD6  10U_0603_10V6M  [C_0603]  75.41 13.59 270 top
CD7  10U_0603_10V6M  [C_0603]  71.72 4.07 90 top
CD8  10U_0603_10V6M  [C_0603]  59.95 13.86 270 top
CD9  1U_0402_6.3V6K  [C_0402]  101.99 10.06 270 top
CD10  1U_0402_6.3V6K  [C_0402]  69.82 13.35 270 top
CD11  1U_0402_6.3V6K  [C_0402]  69.95 4.31 90 top
CD12  1U_0402_6.3V6K  [C_0402]  71.51 13.36 270 top
CD13  1U_0402_6.3V6K  [C_0402]  85.78 6.81 0 top
CD14  1U_0402_6.3V6K  [C_0402]  63.16 5.27 180 top
CD15  1U_0402_6.3V6K  [C_0402]  57.92 13.1 90 top
CD16  1U_0402_6.3V6K  [C_0402]  47.47 13.48 270 top
CD17  330U_D3_2.5VY_R6M  [C_D3]  85.63 13.12 90 top
CD18  1U_0402_6.3V6K  [C_0402]  106.65 10.66 90 top
CD19  1U_0402_6.3V6K  [C_0402]  105.76 10.66 90 top
CD20  10U_0603_10V6M  [C_0603]  109.06 10.42 90 top
CD21  10U_0603_10V6M  [C_0603]  107.79 10.42 90 top
CD22  10U_0603_10V6M  [C_0603]  106.81 3.95 270 top
CD23  1U_0402_6.3V6K  [C_0402]  106.86 6.05 0 top
CD24  1U_0402_6.3V6K  [C_0402]  106.86 5.03 0 top
CD25  0.1U_0402_10V6K  [C_0402]  81.92 5.24 270 top
CD26  2.2U_0402_6.3V6M  [C_0402]  82.94 5.24 270 top
CD27  2.2U_0402_6.3V6M  [C_0402]  104.82 8.95 180 top
CD28  0.1U_0201_10V6K  [C_0201]  104.65 9.72 180 top
CD29  0.1U_0402_25V6  [C_0402]  65.88 5.27 180 top
CD31  0.022U_0402_16V7K  [C_0402]  83.75 3.25 0 top
CD32  0.1U_0201_10V6K  [C_0201]  90.52 12.56 90 top
CD33  10U_0603_10V6M  [C_0603]  155.33 15.89 270 top
CD34  10U_0603_10V6M  [C_0603]  157.61 15.89 270 top
CD35  10U_0603_10V6M  [C_0603]  147.39 15.19 180 top
CD36  10U_0603_10V6M  [C_0603]  153.8 15.89 270 top
CD37  10U_0603_10V6M  [C_0603]  170.06 12.46 90 top
CD38  10U_0603_10V6M  [C_0603]  150.5 14.49 90 top
CD39  10U_0603_10V6M  [C_0603]  140.03 13.72 270 top
CD40  10U_0603_10V6M  [C_0603]  127.33 12.32 90 top
CD41  1U_0402_6.3V6K  [C_0402]  167.07 7.05 90 top
CD42  1U_0402_6.3V6K  [C_0402]  171.33 12.7 90 top
CD43  1U_0402_6.3V6K  [C_0402]  180.98 10.92 90 top
CD44  1U_0402_6.3V6K  [C_0402]  134.12 5.27 0 top
CD45  1U_0402_6.3V6K  [C_0402]  125.34 5.29 0 top
CD46  1U_0402_6.3V6K  [C_0402]  128.48 12.56 90 top
CD47  1U_0402_6.3V6K  [C_0402]  138.89 13.48 270 top
CD48  1U_0402_6.3V6K  [C_0402]  177.19 5.27 180 top
CD49  330U_D3_2.5VY_R6M  [C_D3]  165.21 18.31 0 top
CD50  1U_0402_6.3V6K  [C_0402]  189.21 12.29 90 top
CD51  1U_0402_6.3V6K  [C_0402]  189.11 11.08 270 top
CD52  10U_0603_10V6M  [C_0603]  190.38 12.21 90 top
CD53  10U_0603_10V6M  [C_0603]  190.38 11.06 270 top
CD54  10U_0603_10V6M  [C_0603]  190.12 6.49 270 top
CD55  1U_0402_6.3V6K  [C_0402]  188.85 6 270 top
CD56  1U_0402_6.3V6K  [C_0402]  187.84 6 270 top
CD57  0.1U_0402_10V6K  [C_0402]  169.45 4.4 90 top
CD58  2.2U_0402_6.3V6M  [C_0402]  168.43 4.4 90 top
CD59  2.2U_0402_6.3V6M  [C_0402]  186.57 12.19 90 top
CD60  0.1U_0201_10V6K  [C_0201]  185.81 12.36 90 top
CD61  0.1U_0402_25V6  [C_0402]  141.46 3.76 180 top
CD62  0.022U_0402_16V7K  [C_0402]  172.22 2.29 90 top
CE1  0.1U_0402_25V6K  [C_0402]  47.88 74.14 270 bottom
CE2  1U_0402_6.3V6K  [C_0402]  46.87 74.14 270 bottom
CE3  2200P_0402_50V7K  [C_0402]  304.84 68.89 0 top
CE4  2200P_0402_50V7K  [C_0402]  309.29 68.93 270 top
CE5  3300P_0402_50V7-K  [C_0402]  279.57 78.67 180 top
CE6  0.1U_0402_25V6K  [C_0402]  280.5 75.71 180 top
CE8  .047U_0402_16V7K  [C_0402]  307.46 84.16 0 top
CE10  1U_0402_6.3V6K  [C_0402]  284.87 69.92 90 top
CE11  0.1U_0201_10V6K  [C_0201]  290.14 77.19 180 top
CE12  2.2U_0402_6.3V6M  [C_0402]  287.91 70.83 270 top
CE13  0.1U_0201_10V6K  [C_0201]  293.48 75.88 270 top
CE14  1U_0402_6.3V6K  [C_0402]  291.06 76.34 180 top
CE15  0.1U_0201_10V6K  [C_0201]  301.37 69.5 180 top
CE16  10U_0603_6.3V6M  [C_0603]  306.98 64.39 90 top
CE17  22U_0603_6.3V6M  [C_0603]  299.35 68.62 0 top
CE18  0.1U_0201_10V6K  [C_0201]  299.53 69.63 0 top
CE19  0.1U_0201_10V6K  [C_0201]  307.66 78.75 0 top
CE20  0.1U_0201_10V6K  [C_0201]  307.65 78.15 0 top
CE21  0.1U_0201_10V6K  [C_0201]  308.15 75.57 0 top
CE22  0.1U_0201_10V6K  [C_0201]  310.51 72.25 0 top
CE23  0.1U_0201_10V6K  [C_0201]  300.84 66.8 180 top
CE24  2200P_0402_50V7K  [C_0402]  292.93 77.63 270 top
CE25  0.1U_0201_10V6K  [C_0201]  304.63 86.89 90 top
CE26  2200P_0402_50V7K  [C_0402]  291.98 79.15 270 top
CE27  2200P_0402_50V7K  [C_0402]  292.93 80.55 270 top
CE28  10P_0402_50V8J  [C_0402]  292.63 71.16 270 top
CE29  10P_0402_50V8J  [C_0402]  292.37 72.2 90 top
CE30  1U_0402_6.3V6K  [C_0402]  300.09 83.94 90 top
CE31  1U_0402_6.3V6K  [C_0402]  303.74 68.82 270 top
CE32  10U_0603_6.3V6M  [C_0603]  266.29 39.98 220 top
CE35  100P_0402_50V8J  [C_0402]  124.12 57.66 90 top
CE36  0.1U_0402_25V6  [C_0402]  285.37 73.12 270 top
CE37  100P_0402_50V8J  [C_0402]  238.69 11.96 0 bottom
CE38  0.1U_0402_25V6  [C_0402]  293.32 81.68 180 top
CE39  100P_0402_50V8J  [C_0402]  79.14 45.61 180 top
CE40  4700P_0402_25V7K  [C_0402]  302.65 86.12 0 top
CE46  100P_0402_50V8J  [C_0402]  113.67 11.32 180 bottom
CE47  4700P_0402_25V7K  [C_0402]  301.63 88.97 90 top
CE52  0.1U_0402_25V6K  [C_0402]  305.39 91.46 180 top
CE53  0.1U_0402_25V6K  [C_0402]  308.49 92.42 270 top
CE54  10P_0402_50V8J  [C_0402]  298.07 63.85 270 top
CE57  33P_0402_50V8J  [C_0402]  285.95 79.28 270 top
CE59  12P_0402_50V8J  [C_0402]  314.97 72.2 90 top
CE60  68P_0402_50V8J  [C_0402]  313.95 72.2 90 top
CE61  68P_0402_50V8J  [C_0402]  303.54 88.03 270 top
CE62  4700P_0402_25V7K  [C_0402]  298.9 67.21 270 top
CE500  1U_0402_6.3V6K  [C_0402]  42.44 81.95 180 bottom
CE503  1U_0402_6.3V6K  [C_0402]  293.62 85.48 180 top
CE504  10P_0402_50V8J  [C_0402]  306.9 79.56 90 bottom
CE505  10P_0402_50V8J  [C_0402]  306.04 79.56 90 bottom
CI1  100U_1206_6.3V6M  [C_1206]  19.62 76.33 270 top
CI3  0.1U_0201_10V6K  [C_0201]  20.89 78.24 90 top
CI4  0.1U_0402_25V6  [C_0402]  21.21 72.54 0 top
CI5  0.1U_0402_25V6  [C_0402]  21.21 71.65 0 top
CI6  10U_0603_10V6M  [C_0603]  25.15 75.71 0 top
CI7  0.1U_0201_10V6K  [C_0201]  25.24 76.66 0 top
CI8  100U_1206_6.3V6M  [C_1206]  87.32 102.25 0 bottom
CI10  0.1U_0201_10V6K  [C_0201]  85.86 103.9 180 bottom
CI11  10U_0603_10V6M  [C_0603]  81.22 99.59 180 bottom
CI12  0.1U_0201_10V6K  [C_0201]  82.3 99.75 270 bottom
CI13  0.1U_0402_25V6  [C_0402]  307.68 53.61 180 top
CI14  100U_1206_6.3V6M  [C_1206]  306.58 39.26 180 bottom
CI16  0.1U_0402_25V6  [C_0402]  307.68 52.6 180 top
CI17  0.1U_0201_10V6K  [C_0201]  309.89 44.21 180 top
CI19  0.1U_0201_10V6K  [C_0201]  309.5 63.31 90 top
CI27  0.1U_0402_25V6  [C_0402]  81.67 100.55 270 top
CI28  0.1U_0402_25V6  [C_0402]  82.68 100.55 270 top
CI29  0.1U_0402_25V6  [C_0402]  294.71 48.9 90 top
CI30  0.1U_0402_25V6  [C_0402]  295.6 48.9 90 top
CI31  10U_0402_6.3V6M  [C_0402]  305.69 60.65 90 top
CI32  150U_B2_6.3VM_R35M  [C_B2-NPM]  306.62 39.07 0 bottom
CI33  47U_0603_6.3V6M  [C_0603]  305.69 58.76 270 top
CI34  47U_0603_6.3V6M  [C_0603]  310.51 63.26 0 top
CI37  0.1U_0402_16V4Z  [C_0402]  304.68 60.65 90 top
CI38  0.01UF_0402_25V7K  [C_0402]  299.22 52.67 270 top
CI39  0.1U_0402_10V7K  [C_0402]  297.77 57.68 180 top
CI40  0.1U_0402_10V7K  [C_0402]  297.77 56.66 180 top
CI41  0.1U_0402_10V7K  [C_0402]  296.85 55.64 0 top
CI42  0.1U_0402_10V7K  [C_0402]  296.85 54.63 0 top
CI43  12P_0402_50V8J  [C_0402]  310.77 46.5 180 top
CI44  68P_0402_50V8J  [C_0402]  310.77 45.61 180 top
CI45  12P_0402_50V8J  [C_0402]  20.13 78.24 90 top
CI46  68P_0402_50V8J  [C_0402]  19.24 78.24 90 top
CI47  12P_0402_50V8J  [C_0402]  87.18 103.78 0 bottom
CI48  68P_0402_50V8J  [C_0402]  86.06 103.02 180 bottom
CL1  0.1U_0402_25V6  [C_0402]  275.21 79.57 90 top
CL2  0.1U_0402_25V6  [C_0402]  276.23 79.57 90 top
CL3  0.1U_0201_10V6K  [C_0201]  285.96 86.57 270 top
CL4  10U_0603_10V6M  [C_0603]  286.9 87.14 270 top
CL5  0.1U_0402_25V6  [C_0402]  277.25 79.57 90 top
CL6  0.1U_0402_25V6  [C_0402]  278.26 79.57 90 top
CL7  0.1U_0201_10V6K  [C_0201]  279.53 88.96 270 bottom
CL8  0.1U_0201_10V6K  [C_0201]  274.45 80.57 270 top
CL9  0.1U_0201_10V6K  [C_0201]  276.23 82.53 90 bottom
CL10  0.1U_0201_10V6K  [C_0201]  276.99 82.53 90 bottom
CL11  0.1U_0201_10V6K  [C_0201]  278.77 88.96 270 bottom
CL12  22U_0603_6.3V6M  [C_0603]  279.47 82.57 180 bottom
CL13  27P_0402_50V8J  [C_0402]  286.39 89.38 270 top
CL14  27P_0402_50V8J  [C_0402]  284.36 89.35 90 top
CL15  0.1U_0201_10V6K  [C_0201]  270.64 89.39 90 top
CL16  0.1U_0201_10V6K  [C_0201]  301.63 92.69 90 top
CL17  0.1U_0201_10V6K  [C_0201]  298.58 92.69 90 top
CL18  470P_0402_50V7K  [C_0402]  277.51 104.03 180 top
CL19  0.1U_0201_10V6K  [C_0201]  304.68 96.79 180 top
CL20  0.1U_0201_10V6K  [C_0201]  295.79 92.69 90 top
CL21  0.1U_0201_10V6K  [C_0201]  292.74 92.69 90 top
CL22  10P_1808_3KV8J  [C_1808]  285.88 94.74 90 bottom
CL28  22U_0805_6.3V6M  [C_0805]  283.34 83.58 0 top
CL29  12P_0402_50V8J  [C_0402]  274.83 86.25 0 bottom
CL30  82P_0402_50V8J  [C_0402]  278.01 88.87 270 bottom
CLIP1  -  [CLIP_SH1506X616]  244.25 31.25 0 top
CMOS1  SHORT PADS~D  [SHORTPADS-NPM]  152.63 51.89 270 bottom
CN1  10U_0603_10V6M  [C_0603]  273.37 42.31 180 bottom
CN2  0.1U_0201_10V6K  [C_0201]  274.41 42.31 0 bottom
CN3  0.1U_0201_10V6K  [C_0201]  274.55 46.38 0 bottom
CN4  0.01UF_0402_25V7K  [C_0402]  270.64 36.9 90 bottom
CN5  0.01UF_0402_25V7K  [C_0402]  271.66 36.9 90 bottom
CN6  0.01UF_0402_25V7K  [C_0402]  272.67 36.9 90 bottom
CN7  0.01UF_0402_25V7K  [C_0402]  273.69 36.9 90 bottom
CN8  1000P_0402_50V7K  [C_0402]  280.34 36.72 0 bottom
CN9  0.1U_0201_10V6K  [C_0201]  278.68 36.72 180 bottom
CN10  0.1U_0201_10V6K  [C_0201]  275.08 37.58 180 bottom
CN11  0.1U_0201_10V6K  [C_0201]  275.08 36.82 180 bottom
CN12  0.01UF_0402_25V7K  [C_0402]  280.55 68.29 270 top
CN13  0.01UF_0402_25V7K  [C_0402]  279.6 68.29 270 top
CN14  0.01UF_0402_25V7K  [C_0402]  278.64 68.29 270 top
CN15  0.01UF_0402_25V7K  [C_0402]  277.69 68.29 270 top
CN16  0.01UF_0402_25V7K  [C_0402]  280.66 65.44 0 top
CN17  0.1U_0201_10V6K  [C_0201]  272.84 61.93 180 top
CN20  0.1U_0201_10V6K  [C_0201]  260.96 50.25 180 top
CN21  0.01UF_0402_25V7K  [C_0402]  260.88 51.01 180 top
CN22  0.22U_0402_10V6K  [C_0402]  258.63 48.53 0 top
CN23  0.22U_0402_10V6K  [C_0402]  258.63 47.52 0 top
CN26  0.22U_0402_10V6K  [C_0402]  258.63 45.48 0 top
CN27  0.22U_0402_10V6K  [C_0402]  258.63 46.5 0 top
CN30  0.1U_0201_10V6K  [C_0201]  287.91 54.5 0 bottom
CN31  0.01UF_0402_25V7K  [C_0402]  294.26 58.44 0 top
CN32  0.22U_0402_10V6K  [C_0402]  286.37 52.4 0 bottom
CN33  0.22U_0402_10V6K  [C_0402]  286.39 51.45 0 bottom
CN36  0.22U_0402_10V6K  [C_0402]  290.77 51.38 90 bottom
CN37  0.22U_0402_10V6K  [C_0402]  289.88 51.38 90 bottom
CN60  68P_0402_50V8J  [C_0402]  306.15 27.77 180 top
CN61  0.1U_0201_10V6K  [C_0201]  290.11 27.64 180 top
CN62  0.1U_0201_10V6K  [C_0201]  304.55 27.6 90 top
CN63  22U_0603_6.3V6M  [C_0603]  291.03 28.85 0 top
CN64  22U_0603_6.3V6M  [C_0603]  291.03 30.05 0 top
CN69  0.22U_0402_10V6K  [C_0402]  283.48 39.64 180 bottom
CN70  0.22U_0402_10V6K  [C_0402]  283.48 38.75 180 bottom
CN71  0.22U_0402_10V6K  [C_0402]  283.48 37.61 180 bottom
CN72  0.22U_0402_10V6K  [C_0402]  283.48 36.72 180 bottom
CR1  4.7U_0402_6.3V6M  [C_0402]  24.26 46.2 270 top
CR2  0.1U_0201_10V6K  [C_0201]  25.02 45.87 270 top
CR3  0.1U_0201_10V6K  [C_0201]  27.52 54.28 0 top
CR4  10U_0402_6.3V6M  [C_0402]  26.66 54.29 90 top
CR5  4.7U_0603_6.3V6K  [C_0603]  25.41 55.33 180 top
CR6  0.1U_0201_10V6K  [C_0201]  25.21 54.13 0 top
CR7  0.1U_0201_10V6K  [C_0201]  28.71 54.01 90 top
CR11  0.1U_0402_25V6  [C_0402]  31.39 49.1 180 top
CR12  0.1U_0402_25V6  [C_0402]  31.39 49.99 180 top
CR13  0.1U_0402_25V6  [C_0402]  31.39 50.95 180 top
CR14  0.1U_0402_25V6  [C_0402]  31.39 51.83 180 top
CR15  1U_0402_6.3V6K  [C_0402]  21.67 47.77 180 top
CR17  0.1U_0201_10V6K  [C_0201]  32.43 44.72 180 top
CR18  4.7U_0603_6.3V6K  [C_0603]  31.88 47.2 270 top
CR19  0.1U_0201_10V6K  [C_0201]  6.74 59.86 90 top
CR20  4.7U_0603_6.3V6K  [C_0603]  7.69 59.52 90 top
CR21  5P_0402_50V8C  [C_0402]  20.71 53.69 270 top
CR22  1U_0402_6.3V6K  [C_0402]  21.67 51.83 180 top
CR25  12P_0402_50V8J  [C_0402]  21.83 43.08 270 top
CR26  82P_0402_50V8J  [C_0402]  20.82 43.08 270 top
CR27  12P_0402_50V8J  [C_0402]  23.25 46.2 270 top
CR28  82P_0402_50V8J  [C_0402]  22.23 46.2 270 top
CT70  .1U_0402_16V7K  [C_0402]  33.91 99.13 90 bottom
CT71  2.2U_0402_16V6K  [C_0402]  33.53 84.65 90 top
CT72  2.2U_0402_16V6K  [C_0402]  37.46 84.6 0 top
CT73  2.2U_0402_16V6K  [C_0402]  26.81 84.85 180 top
CT74  1U_0402_16V6K  [C_0402]  30.92 86 0 top
CT75  22U_0805_25V6M  [C_0805]  41.84 92.01 270 top
CT76  22U_0805_25V6M  [C_0805]  45.68 92.04 270 top
CT77  22U_0805_25V6M  [C_0805]  43.81 92 270 top
CT78  22U_0805_25V6M  [C_0805]  45.7 92.04 270 bottom
CT80  0.1U_0201_10V6K  [C_0201]  29.09 87.43 270 top
CT81  0.1U_0201_10V6K  [C_0201]  28.33 87.43 270 top
CT82  1U_0603_25V6K  [C_0603]  37.15 76.15 0 top
CT83  1U_0402_16V6K  [C_0402]  29.07 84.21 270 bottom
CT84  10U_0603_6.3V6M  [C_0603]  40.37 85.91 90 top
CT85  470P_0402_50V7K  [C_0402]  28.26 75.6 270 top
CT86  470P_0402_50V7K  [C_0402]  25.86 77.55 180 top
CT87  0.22U_0402_16V7K  [C_0402]  30.36 79.53 270 bottom
CT88  0.1U_0201_10V6K  [C_0201]  40.73 97.3 0 bottom
CT89  1U_0402_10V6K  [C_0402]  40.57 96.28 0 bottom
CT90  1U_0402_10V6K  [C_0402]  39.5 100.81 270 bottom
CT91  2.2U_0603_25V6K  [C_0603]  44.84 99.17 90 bottom
CT92  0.1U_0402_25V6K  [C_0402]  43.26 97.05 180 bottom
CT93  1U_0402_10V6K  [C_0402]  24.2 89.88 270 bottom
CT94  1U_0603_50V6K  [C_0603]  17.72 84.35 270 bottom
CT95  0.22U_0201_6.3V6K  [C_0201]  13.22 94.24 180 bottom
CT96  0.22U_0201_6.3V6K  [C_0201]  13.22 95 180 bottom
CT97  0.22U_0201_6.3V6K  [C_0201]  13.22 100.84 180 top
CT98  0.22U_0201_6.3V6K  [C_0201]  13.22 100.03 180 top
CT99  0.47U_0201_25V  [C_0201]  7.96 95.58 270 top
CT100  0.47U_0201_25V  [C_0201]  8.54 95.58 270 top
CT101  0.47U_0201_25V  [C_0201]  8.26 98.02 90 top
CT102  0.47U_0201_25V  [C_0201]  7.5 98.02 90 top
CT103  0.1U_0402_25V6  [C_0402]  26.24 98.57 180 bottom
CT104  0.1U_0402_25V6  [C_0402]  26.24 97.55 180 bottom
CT105  0.1U_0402_25V6  [C_0402]  26.24 96.54 180 bottom
CT106  0.1U_0402_25V6  [C_0402]  26.24 95.52 180 bottom
CT107  0.1U_0402_25V6  [C_0402]  26.24 94.51 180 bottom
CT108  0.1U_0402_25V6  [C_0402]  26.24 93.49 180 bottom
CT109  0.1U_0402_25V6  [C_0402]  26.24 92.47 180 bottom
CT110  0.1U_0402_25V6  [C_0402]  26.24 91.46 180 bottom
CT111  0.1U_0402_25V6  [C_0402]  22.48 100.81 270 bottom
CT112  0.1U_0402_25V6  [C_0402]  21.47 100.81 270 bottom
CT113  0.1U_0402_25V6  [C_0402]  24.52 100.81 270 bottom
CT114  0.1U_0402_25V6  [C_0402]  23.5 100.81 270 bottom
CT115  0.1U_0402_25V6  [C_0402]  22.36 88.84 90 bottom
CT116  0.1U_0402_25V6  [C_0402]  21.47 88.84 90 bottom
CT117  10U_0402_6.3V6M  [C_0402]  21.98 97.76 270 top
CT118  0.1U_0201_10V6K  [C_0201]  20.45 91.42 90 top
CT119  0.1U_0201_10V6K  [C_0201]  21 97.81 180 top
CT120  0.1U_0201_10V6K  [C_0201]  19.69 91.42 90 top
CT121  0.1U_0201_10V6K  [C_0201]  23.25 92.69 90 top
CT122  2.2U_0402_6.3V6M  [C_0402]  17.4 99.89 90 bottom
CT189  12P_0402_50V8J  [C_0402]  9.02 98.11 90 top
CT190  82P_0402_50V8J  [C_0402]  9.3 95.49 270 top
CV1  0.1U_0402_25V6  [C_0402]  98.42 87.9 90 bottom
CV2  0.1U_0402_25V6  [C_0402]  97.54 87.9 90 bottom
CV3  0.1U_0402_25V6  [C_0402]  96.65 87.89 90 bottom
CV4  0.1U_0402_25V6  [C_0402]  95.76 87.89 90 bottom
CV5  0.1U_0402_25V6  [C_0402]  94.87 87.89 90 bottom
CV6  0.1U_0402_25V6  [C_0402]  93.86 87.89 90 bottom
CV11  0.1U_0603_50V7K  [C_0603]  108.58 86.42 0 bottom
CV12  0.1U_0201_10V6K  [C_0201]  101.96 88.94 0 bottom
CV13  1000P_0402_50V7K  [C_0402]  106.56 81.79 90 bottom
CV14  0.01U_0402_50V7K  [C_0402]  104.53 81.79 90 bottom
CV15  0.1U_0603_50V7K  [C_0603]  108.58 85.15 0 bottom
CV16  10U_0603_10V6M  [C_0603]  100.14 86.31 180 bottom
CV17  0.01UF_0402_25V7K  [C_0402]  97.29 85.35 90 bottom
CV18  12P_0402_50V8J  [C_0402]  121.16 88.8 270 bottom
CV19  82P_0402_50V8J  [C_0402]  122.18 88.8 270 bottom
CV20  12P_0402_50V8J  [C_0402]  101.1 86.25 0 bottom
CV21  82P_0402_50V8J  [C_0402]  101.62 88.12 0 bottom
CV22  12P_0402_50V8J  [C_0402]  111.82 88.09 0 bottom
CV23  82P_0402_50V8J  [C_0402]  111.82 87.07 0 bottom
CV24  12P_0402_50V8J  [C_0402]  108.46 88.79 0 bottom
CV25  82P_0402_50V8J  [C_0402]  108.46 87.9 0 bottom
CV31  0.1U_0402_25V6  [C_0402]  98.18 101.22 90 top
CV32  0.1U_0402_25V6  [C_0402]  99.19 101.22 90 top
CV33  0.1U_0402_25V6  [C_0402]  101.54 101.29 90 top
CV34  0.1U_0402_25V6  [C_0402]  102.49 101.29 90 top
CV35  0.1U_0402_25V6  [C_0402]  108.34 100.21 90 top
CV36  0.1U_0402_25V6  [C_0402]  109.35 100.21 90 top
CV37  0.1U_0402_25V6  [C_0402]  105.29 102.14 270 top
CV38  0.1U_0402_25V6  [C_0402]  106.3 102.14 270 top
CV39  0.1U_0201_10V6K  [C_0201]  116.65 104.38 90 top
CV40  0.1U_0201_10V6K  [C_0201]  112.19 108.17 90 top
CV41  10U_0603_10V6M  [C_0603]  113.13 108.3 90 top
CV80  0.01UF_0402_25V7K  [C_0402]  106.69 101.87 90 bottom
CV81  0.01UF_0402_25V7K  [C_0402]  94.75 91.2 180 top
CV82  0.01UF_0402_25V7K  [C_0402]  100.97 86 270 top
CV83  0.1U_0201_10V6K  [C_0201]  94.75 90.44 180 top
CV84  0.1U_0201_10V6K  [C_0201]  107.45 101.87 90 bottom
CV85  0.1U_0201_10V6K  [C_0201]  100.72 89.68 270 top
CV86  0.1U_0201_10V6K  [C_0201]  101.36 89.34 90 top
CV87  0.1U_0201_10V6K  [C_0201]  102 89.34 90 top
CV88  0.1U_0201_10V6K  [C_0201]  102.63 89.34 90 top
CV89  0.1U_0201_10V6K  [C_0201]  103.27 89.34 90 top
CV90  0.1U_0201_10V6K  [C_0201]  103.9 89.34 90 top
CV91  0.1U_0201_10V6K  [C_0201]  104.54 89.34 90 top
CV92  0.1U_0201_10V6K  [C_0201]  105.43 89.34 90 top
CV93  0.1U_0201_10V6K  [C_0201]  106.06 89.34 90 top
CV94  0.1U_0201_10V6K  [C_0201]  93.86 93.24 0 top
CV95  0.1U_0201_10V6K  [C_0201]  93.88 93.83 0 top
CV96  2.2U_0402_6.3V6M  [C_0402]  96.02 99.97 90 top
CV100  0.1U_0402_25V6  [C_0402]  281.72 56.91 90 top
CV101  0.1U_0402_25V6  [C_0402]  282.19 53.42 0 top
CV102  4.7U_0402_6.3V6M  [C_0402]  282.19 54.37 0 top
CV103  0.1U_0402_25V6  [C_0402]  273.51 56.34 180 bottom
CV104  0.1U_0402_25V6  [C_0402]  278.69 59.5 0 bottom
CV105  2.2U_0402_16V6K  [C_0402]  278.69 58.62 0 bottom
CV106  0.1U_0402_25V6  [C_0402]  277.88 57.3 270 bottom
CV107  0.1U_0402_10V7K  [C_0402]  272.6 55.45 0 bottom
CV108  0.1U_0402_10V7K  [C_0402]  272.6 54.56 0 bottom
CV109  0.1U_0402_10V7K  [C_0402]  272.6 53.67 0 bottom
CV110  0.1U_0402_10V7K  [C_0402]  272.6 52.78 0 bottom
CV111  0.1U_0402_10V7K  [C_0402]  272.85 58.5 0 bottom
CV112  0.1U_0402_10V7K  [C_0402]  272.85 57.36 0 bottom
CV126  12P_0402_50V8J  [C_0402]  317.38 90.43 90 bottom
CV127  12P_0402_50V8J  [C_0402]  315.09 90.43 90 bottom
CV128  12P_0402_50V8J  [C_0402]  313.63 75.09 270 bottom
CV129  3.3P_0402_50V8C  [C_0402]  317.43 87.58 0 bottom
CV130  3.3P_0402_50V8C  [C_0402]  316.06 87.58 180 bottom
CV131  3.3P_0402_50V8C  [C_0402]  313.52 77.68 180 bottom
CV132  22P_0402_50V8J  [C_0402]  317.63 76.36 270 top
CV133  22P_0402_50V8J  [C_0402]  317.63 78.64 270 top
CV134  1U_0402_6.3V6K  [C_0402]  318.39 77.12 270 bottom
CV135  0.1U_0402_16V4Z  [C_0402]  318.39 75.09 270 bottom
CV145  0.1U_0402_25V6  [C_0402]  197.81 20.85 0 bottom
CV146  0.1U_0402_25V6  [C_0402]  197.81 19.83 0 bottom
CV147  0.1U_0402_25V6  [C_0402]  197.81 17.8 0 bottom
CV148  0.1U_0402_25V6  [C_0402]  197.81 18.81 0 bottom
CV149  0.1U_0402_25V6  [C_0402]  203.84 29.18 270 bottom
CV150  0.1U_0402_25V6  [C_0402]  204.86 29.18 270 bottom
CV152  0.1U_0402_25V6  [C_0402]  202.82 29.18 270 bottom
CV153  0.1U_0402_25V6  [C_0402]  201.81 29.18 270 bottom
CV156  0.1U_0402_25V6  [C_0402]  200.79 29.18 270 bottom
CV157  0.1U_0402_25V6  [C_0402]  199.78 29.18 270 bottom
CZ1  100P_0201_25V7K  [C_0201]  111.85 88.85 0 bottom
CZ2  0.1U_0201_10V6K  [C_0201]  120.4 88.89 270 bottom
CZ3  100P_0402_50V8J  [C_0402]  80.9 96.54 0 bottom
CZ10  0.1U_0402_25V6  [C_0402]  292.28 65.61 0 bottom
CZ11  0.1U_0402_25V6  [C_0402]  292.28 66.57 0 bottom
CZ12  0.1U_0402_25V6  [C_0402]  197.81 16.78 0 bottom
CZ13  0.1U_0402_25V6  [C_0402]  197.81 15.77 0 bottom
CZ14  0.1U_0402_25V6  [C_0402]  197.81 10.69 0 bottom
CZ15  0.1U_0402_25V6  [C_0402]  197.81 9.67 0 bottom
CZ17  .047U_0402_16V7K  [C_0402]  282.64 47.5 90 bottom
CZ18  .047U_0402_16V7K  [C_0402]  283.53 47.5 90 bottom
CZ19  33P_0402_50V8J  [C_0402]  303.66 47.02 270 top
CZ20  22U_0603_6.3V6M  [C_0603]  282.77 46.37 270 bottom
CZ21  33P_0402_50V8J  [C_0402]  303.13 48.89 90 top
CZ23  47P_0402_50V8J  [C_0402]  304.02 48.89 90 top
CZ24  100P_0402_50V8J  [C_0402]  304.91 48.89 90 top
CZ25  2000P_0402_50V7K  [C_0402]  304.55 47.02 270 top
CZ26  100U_B2_6.3VM_R35M  [C_B2]  309.5 47.24 90 bottom
CZ27  10U_0603_10V6M  [C_0603]  214.89 6.43 0 top
CZ28  0.01UF_0402_25V7K  [C_0402]  207.14 30.8 90 bottom
CZ29  0.01UF_0402_25V7K  [C_0402]  214.76 5.3 270 top
CZ30  0.1U_0201_10V6K  [C_0201]  214.85 7.38 0 top
CZ31  0.1U_0201_10V6K  [C_0201]  206.93 27.96 180 bottom
CZ32  4.7U_0603_6.3V6K  [C_0603]  205.87 30.82 90 bottom
CZ33  15P_0402_50V8J  [C_0402]  207.09 28.72 180 bottom
CZ34  15P_0402_50V8J  [C_0402]  207.09 29.74 180 bottom
CZ35  15P_0402_50V8J  [C_0402]  214.81 8.15 0 top
CZ36  15P_0402_50V8J  [C_0402]  215.78 5.3 270 top
CZ37  4.7U_0402_6.3V6M  [C_0402]  117.78 112.41 0 bottom
CZ38  47P_0402_50V8J  [C_0402]  118.69 109.76 270 bottom
CZ39  33P_0402_50V8J  [C_0402]  118.69 110.62 90 bottom
CZ40  33P_0402_50V8J  [C_0402]  132.47 100.22 0 bottom
CZ41  0.1U_0402_25V6  [C_0402]  125.53 102.66 270 top
CZ50  0.1U_0201_10V6K  [C_0201]  170.82 39.48 90 top
CZ51  0.1U_0201_10V6K  [C_0201]  170.12 33.67 180 top
CZ52  10U_0603_10V6M  [C_0603]  170.19 32.72 180 top
CZ53  0.1U_0201_10V6K  [C_0201]  163.07 36.06 270 top
CZ54  0.1U_0201_10V6K  [C_0201]  166.31 41.51 90 top
CZ55  10U_0603_10V6M  [C_0603]  168.98 41.93 90 top
CZ56  0.1U_0402_25V6  [C_0402]  161.05 37.99 180 top
CZ57  12P_0402_50V8J  [C_0402]  181.41 32.09 0 top
CZ58  68P_0402_50V8J  [C_0402]  181.41 32.97 0 top
CZ59  12P_0402_50V8J  [C_0402]  159.26 40.29 270 top
CZ60  68P_0402_50V8J  [C_0402]  158.37 40.29 270 top
CZ61  .047U_0402_16V7K  [C_0402]  219.14 19.53 270 top
CZ62  68P_0402_50V8J  [C_0402]  221.06 10.43 180 top
CZ63  68P_0402_50V8J  [C_0402]  221.06 11.7 180 top
CZ64  0.1U_0201_10V6K  [C_0201]  221.11 14.75 270 top
CZ66  0.1U_0201_10V6K  [C_0201]  220.99 17.93 90 top
CZ67  0.1U_0201_10V6K  [C_0201]  221.11 16.02 270 top
CZ68  0.1U_0201_10V6K  [C_0201]  220.22 12.72 180 top
CZ69  68P_0402_50V8J  [C_0402]  220.35 14.5 180 top
CZ71  68P_0402_50V8J  [C_0402]  220.1 17.8 90 top
CZ72  68P_0402_50V8J  [C_0402]  220.35 15.77 180 top
CZ73  68P_0402_50V8J  [C_0402]  220.35 13.48 180 top
CZ75  4.7U_0402_6.3V6M  [C_0402]  171.58 39.44 90 top
CZ80  10P_0402_50V8J  [C_0402]  215.83 26.18 0 top
CZ81  10P_0402_50V8J  [C_0402]  215.83 23.13 0 top
CZ82  0.1U_0201_10V6K  [C_0201]  138.05 30.75 0 top
CZ83  68P_0402_50V8J  [C_0402]  215.76 18.32 270 top
CZ84  68P_0402_50V8J  [C_0402]  214.81 11.96 0 top
CZ85  68P_0402_50V8J  [C_0402]  215.4 14.75 0 top
CZ86  68P_0402_50V8J  [C_0402]  215.4 15.64 0 top
CZ87  68P_0402_50V8J  [C_0402]  214.81 16.53 0 top
CZ88  68P_0402_50V8J  [C_0402]  217.11 20.12 0 top
CZ89  68P_0402_50V8J  [C_0402]  217.11 21.14 0 top
CZ90  0.1U_0201_10V6K  [C_0201]  214.74 18.4 270 top
CZ91  0.1U_0201_10V6K  [C_0201]  215.4 13.99 0 top
CZ92  0.1U_0201_10V6K  [C_0201]  215.4 13.35 0 top
CZ93  0.1U_0201_10V6K  [C_0201]  279.91 45.97 270 top
CZ100  1U_0402_6.3V6K  [C_0402]  138.05 86.51 180 bottom
CZ101  0.1U_0201_10V6K  [C_0201]  124.34 84.22 180 bottom
CZ102  1U_0402_6.3V6K  [C_0402]  126.67 26.37 0 top
CZ103  0.1U_0201_10V6K  [C_0201]  123.44 29.37 90 top
CZ104  0.1U_0402_10V7K  [C_0402]  128.96 26.37 0 top
CZ105  1U_0402_6.3V6K  [C_0402]  133.74 83 90 bottom
CZ106  0.1U_0201_10V6K  [C_0201]  144.56 86.63 0 bottom
CZ109  470P_0402_50V7K  [C_0402]  278.72 49.92 0 bottom
CZ110  470P_0402_50V7K  [C_0402]  278.72 50.81 0 bottom
CZ111  0.1U_0201_10V6K  [C_0201]  276.61 52.22 180 bottom
CZ112  0.1U_0201_10V6K  [C_0201]  204.43 9.68 180 top
CZ113  470P_0402_50V7K  [C_0402]  206.05 7.71 0 top
CZ114  1000P_0402_50V7K  [C_0402]  206.05 6.83 0 top
CZ115  0.1U_0201_10V6K  [C_0201]  205.62 4.08 270 top
CZ116  0.1U_0201_10V6K  [C_0201]  194.91 17.8 0 top
CZ117  470P_0402_50V7K  [C_0402]  194.94 17.04 0 top
CZ118  470P_0402_50V7K  [C_0402]  194.94 16.02 0 top
CZ119  0.1U_0201_10V6K  [C_0201]  277.41 46.63 180 bottom
CZ120  0.1U_0201_10V6K  [C_0201]  272.55 49.42 90 top
